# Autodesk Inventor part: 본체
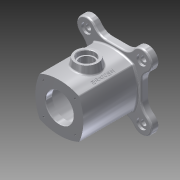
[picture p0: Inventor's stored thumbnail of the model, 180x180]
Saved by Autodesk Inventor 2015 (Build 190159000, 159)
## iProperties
Created: 2016-05
Part Number: 본체
Material: 알루미늄 6061
Document SubType Name: Modeling
Designer: Administrator
Density: 2.7 g/cm^3
Appearance: 알루미늄 - 평지
Mass: 1105.19 g
Surface Area: 862.501 cm^2
Volume: 409.328 cm^3
Author: Administrator
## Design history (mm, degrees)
sketch "스케치1"
  geometry: L1 (0, 0)-(-35.283, 35.427); L2 (0, 0)-(35.283, 35.427); L3 (0, 0)-(-35.575, -35.134); A1 r 86 centre (43, -0.178) between (-35.283, 35.427) and (-35.575, -35.134); A2 r 86 centre (0, -43.002) between (35.283, 35.427) and (-35.283, 35.427); A3 r 86 centre (-43, -0.178) between (35.392, -35.543) and (35.283, 35.427); A4 r 86 centre (0.36, 42.998) between (-35.575, -35.134) and (35.392, -35.543)
  constraints: 8 point on circle, 6 end point, 4 centre point
  dimensions: "d103" = 86 distance of A3.centre A1.centre; "d104" = 43 horizontal distance of A3.centre L1.start; "d105" = 43 horizontal distance of A1.centre L1.start; "d106" = 86 radius of A2; "d107" = 86 radius of A1; "d108" = 86 radius of A3; "d109" = 86 radius of A4; "d110" = 86 vertical distance of A2.centre A4.centre; "d111" = 43 distance of L1.start A4.centre; "d112" = 50 distance of L1.start L1.end; "d113" = 50 distance of L1.start L2.end; "d114" = 50 distance of L1.start L3.end
extrude "돌출1" new body sketch "스케치1" distance "d12" = 98; taper "d13" = 0 deg
sketch "스케치2"
  geometry: L1 (-14.162, -49)-(14.162, -49); L2 (49, -14.162)-(49, 14.162); L3 (14.162, 49)-(-14.162, 49); L4 (-49, 14.162)-(-49, -14.162); L5 (0, 0)-(-70, -70); L6 (0, 0)-(98.995, 0); L7 (0, 0)-(-81.178, 81.178); L8 (0, 0)-(114.803, 0); L9 (0, 0)-(88.016, 88.016); L10 (0, 0)-(124.473, 0); L11 (0, 0)-(82.092, -82.092); L12 (0, 0)-(116.096, 0); A1 r 18 centre (49.497, 49.497) between (59.754, 34.706) and (34.706, 59.754); A2 r 25 centre (74, 14.162) between (59.754, 34.706) and (49, 14.162); A3 r 25 centre (14.162, 74) between (14.162, 49) and (34.706, 59.754); A4 r 18 centre (-49.497, 49.497) between (-34.706, 59.754) and (-59.754, 34.706); A5 r 18 centre (-49.497, -49.497) between (-59.754, -34.706) and (-34.706, -59.754); A6 r 18 centre (49.497, -49.497) between (34.706, -59.754) and (59.754, -34.706); A7 r 25 centre (-74, 14.162) between (-49, 14.162) and (-59.754, 34.706); A8 r 25 centre (-14.162, 74) between (-34.706, 59.754) and (-14.162, 49); A9 r 25 centre (14.162, -74) between (34.706, -59.754) and (14.162, -49); A10 r 25 centre (74, -14.162) between (49, -14.162) and (59.754, -34.706); A11 r 70 centre (0, 0) between (-49.497, -49.497) and (49.497, 49.497); A12 r 25 centre (-74, -14.162) between (-59.754, -34.706) and (-49, -14.162); A13 r 25 centre (-14.162, -74) between (-14.162, -49) and (-34.706, -59.754); 9 further points
  constraints: 38 point on circle, 24 end point, 16 tangent, 13 centre point, 12 point on line, 5 horizontal, 4 equal length, 4 equal radius, 2 parallel, 1 coincident, 1 perpendicular
  dimensions: "d16" = 36 diameter of A1; "d19" = 25 radius of A2; "d20" = 36 diameter of A4; "d21" = 36 diameter of A5; "d22" = 36 diameter of A6; "d23" = 25 radius of A7; "d92" = 140 diameter of A11; "d93" = 25 radius of A12; "d94" = 25 radius of A13; "d95" = 49 distance from line of point (0, 0) L3; "d96" = 49 distance from line of point (0, 0) L2; "d97" = 49 distance from line of L4 point (0, 0); "d98" = 49 distance from line of L1 point (0, 0); "d99" = 135 deg angle of L5 L6; "d100" = 135 deg angle of L8 L7; "d101" = 45 deg angle of L10 L9; "d102" = 45 deg angle of L11 L12
extrude "돌출2" join sketch "스케치2" distance "d24" = 12; taper "d25" = 0 deg
sketch "스케치3"
  geometry: L1 (0, 0)-(25, 0); L2 (25, 0)-(25, 12); L3 (25, 12)-(0, 12); L4 (0, 12)-(0, 0); L5 (14.162, 110)-(34.706, 110) reference; L6 (-14.162, 110)-(14.162, 110) reference; L7 (0, 12)-(32, 12); L8 (35, 15)-(35, 95); L9 (32, 98)-(0, 98); L10 (0, 98)-(0, 12); L11 (0, 98)-(25, 98); L12 (25, 98)-(25, 110); L13 (25, 110)-(0, 110); L14 (0, 110)-(0, 98); A1 r 3 centre (32, 15) between (32, 12) and (35, 15); A2 r 3 centre (32, 95) between (35, 95) and (32, 98)
  constraints: 24 end point, 6 parallel, 4 point on circle, 4 tangent, 3 horizontal, 3 perpendicular, 2 centre point, 1 equal radius, 1 point on line
  dimensions: "d26" = 12 distance of L1.end L2.end; "d27" = 12 distance of L11.end L12.end; "d28" = 25 distance between parallel lines of L12 L14; "d29" = 35 distance between parallel lines of L10 L8; "d30" = 25 distance between parallel lines of L4 L2; "d31" = 3 radius of A1
revolve "회전1" sketch "스케치3" stored, may be unused: angle "d32" = 90 deg
chamfer "모따기1" distance "d33" = 1; stored, may be unused: second distance "d34" = 2, angle "d35" = 45 deg
sketch "스케치4"
  geometry: L1 (55, 69)-(55, 49); L2 (55, 49)-(40.065, 49); L3 (40.065, 49)-(40.065, 71.633); L4 (43, 0)-(43, 98) reference; L5 (55, 69)-(40.065, 71.633); 1 further point
  constraints: 8 end point, 1 parallel
  dimensions: "d36" = 55 distance from line of L1 point (0, 0); "d37" = 100 deg angle of L4 L5; "d39" = 49 distance from line of point (0, 0) L2; "d91" = 20 distance of L1.start L1.end
revolve "회전2" sketch "스케치4" stored, may be unused: angle "d40" = 90 deg
sketch "스케치5"
  geometry: C1 r 20 at (0, 0) reference; 1 further point
hole "구멍1" sketch "스케치5" at (0, 0) diameter "d41" = 25; stored, may be unused: countersink angle "d45" = 90 deg, drill point angle "d47" = 118 deg; dims "d42" = 6, "d43" = 30, "d44" = 8, "d46" = 30
chamfer "모따기2" distance "d48" = 1; stored, may be unused: second distance "d49" = 2, angle "d50" = 45 deg
fillet "모깎기1" dims "d51" = 3
fillet "모깎기2" dims "d52" = 3
sketch "스케치6"
  geometry: A1 r 15 centre (49.497, 49.497) between (58.045, 37.171) and (37.171, 58.045) reference; A2 r 15 centre (-49.497, 49.497) between (-37.171, 58.045) and (-58.045, 37.171) reference; A3 r 15 centre (-49.497, -49.497) between (-58.045, -37.171) and (-37.171, -58.045) reference; 6 further points
  constraints: 1 other
hole "구멍2" sketch "스케치6" at (49.497, 49.497), (-49.497, 49.497), (-49.497, -49.497), (49.497, -49.497) diameter "d53" = 10; stored, may be unused: countersink angle "d57" = 90 deg, drill point angle "d59" = 118 deg; dims "d54" = 6, "d55" = 18, "d56" = 4, "d58" = 30
sketch "스케치7" dims "d60" = 80
  geometry: L1 (0, 0)-(94.446, 0); C1 r 26 at (0, 0) reference; 4 further points
  constraints: 2 end point, 1 coincident, 1 horizontal, 8 other
  dimensions: "d64" = 360 deg dimension on C1.centre point (28.284, -28.284) (derived)
hole "구멍3" sketch "스케치7" at (28.284, -28.284), (28.284, 28.284), (-28.284, 28.284), (-28.284, -28.284) diameter "d66" = 3.242; stored, may be unused: countersink angle "d70" = 90 deg, drill point angle "d72" = 118 deg; dims "d67" = 7, "d68" = 18, "d69" = 4, "d71" = 10
sketch "스케치8" dims "d73" = 80
  geometry: L1 (0, 0)-(48.585, 0); C1 r 26 at (0, 0) reference; 4 further points
  constraints: 2 end point, 1 coincident, 1 horizontal, 8 other
  dimensions: "d77" = 360 deg dimension on C1.centre point (28.284, 28.284) (derived)
hole "구멍4" sketch "스케치8" at (28.284, 28.284), (-28.284, 28.284), (-28.284, -28.284), (28.284, -28.284) diameter "d79" = 3.242; stored, may be unused: countersink angle "d83" = 90 deg, drill point angle "d85" = 118 deg; dims "d80" = 7, "d81" = 18, "d82" = 4, "d84" = 10
node "작업 평면1"
sketch "스케치9"
  geometry: 2 further points
  constraints: 1 other
  dimensions: "d87" = 29 horizontal distance of point (0, 0) point (29, 49); "d88" = 49 vertical distance of point (0, 0) point (29, 49)
feature "엠보싱1" sketch "스케치9" dims "d89" = 0.5, "d90" = 0, "d103" = 86, "d104" = 43, "d105" = 43, "d106" = 86, "d107" = 86, "d108" = 86, "d109" = 86, "d110" = 86, "d111" = 43, "d112" = 50, "d113" = 50, "d114" = 50
node "솔리드1"
other parameters: "d86" = -43
